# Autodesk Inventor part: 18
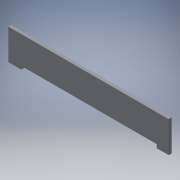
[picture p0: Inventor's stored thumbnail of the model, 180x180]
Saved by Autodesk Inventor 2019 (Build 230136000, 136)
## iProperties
Created: 2019-01
Part Number: 18
Material: Generic
Document SubType Name: Modeling
Designer: Guy Link
Density: 1 g/cm^3
Appearance: Default
Author: Guy Link
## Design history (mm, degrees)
sketch "Sketch1"
  geometry: L1 (-39.841, 23.065)-(126.561, 23.065); L2 (126.561, 23.065)-(126.831, -9.181); L3 (126.831, -9.181)-(114.159, -9.32); L4 (114.159, -9.32)-(114.244, -5.566); L5 (114.244, -5.566)-(-26.45, -5.573); L6 (-26.45, -5.573)-(-26.575, -8.987); L7 (-26.575, -8.987)-(-40.098, -8.802); L8 (-40.098, -8.802)-(-39.841, 23.065); 1 further point
  constraints: 16 end point
extrude "Extrusion1" new body sketch "Sketch1" distance "d0" = 3.175; taper "d1" = 0 deg
body "Solid1"
